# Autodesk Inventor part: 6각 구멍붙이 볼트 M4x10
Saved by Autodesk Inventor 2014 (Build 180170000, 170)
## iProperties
Created: 2026-03
Part Number: 6각 구멍붙이 볼트 M4x10
Material: 일반
Document SubType Name: Modeling
Designer: dg
Density: 1 g/cm^3
Appearance: 기본값
Author: dg
Author: jhkim
Description: 6각머리 태핑 나사
Creation Date: 2025-06-27
Sending System: Autodesk Inventor 2026
Preprocessor: ST-DEVELOPER v20.1
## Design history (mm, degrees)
node "6각 구멍붙이 볼트 M4x101"
body "Solid1"
node "기준1"
